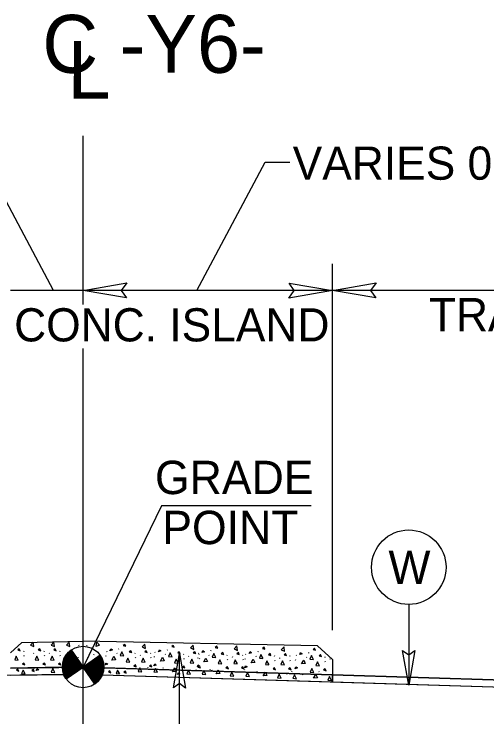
# Model space of a CAD drawing. Extents: x 2176156 to 2177167, y 76401 to 76644.
# Drawn here: x 2176833.29 to 2176849.74, y 76416.24 to 76440.68 of the extents above; entities that cross this region are included whole.
import ezdxf

# ---------------------------------------------------------------- set-up
doc = ezdxf.new("R2010")
doc.units = 0
for name, color, linetype in [('Exist Roads Change in Surface', 7, 'Continuous'), ('Exist Roads Curbs', 7, 'Continuous'), ('Exist Roads Soil', 7, 'Continuous'), ('Exist Structure Minor Culvert Topo', 7, 'Continuous'), ('Exist Vegetation Woods Line', 7, 'Continuous'), ('Old_Level_1', 7, 'Continuous'), ('Old_Level_3', 7, 'Continuous'), ('Prop North Arrow NAD83 for Plan Sheets CELL', 7, 'Continuous')]:
    doc.layers.add(name, color=color, linetype=linetype)

msp = doc.modelspace()

# ---------------------------------------------------------------- linework, layer by layer
at = {"layer": 'Exist Roads Change in Surface'}
for p, q in [((2176835.558, 76418.709), (2176835.547, 76418.733)), ((2176835.825, 76418.709), (2176835.835, 76418.733)), ((2176836.937, 76418.605), (2176836.926, 76418.589)), ((2176833.627, 76418.52), (2176833.617, 76418.504)), ((2176833.647, 76418.345), (2176833.637, 76418.369)), ((2176833.981, 76418.453), (2176833.971, 76418.437)), ((2176834.34, 76418.52), (2176834.329, 76418.504)), ((2176834.36, 76418.345), (2176834.35, 76418.369)), ((2176834.521, 76418.453), (2176834.51, 76418.437)), ((2176834.88, 76418.52), (2176834.869, 76418.504)), ((2176834.9, 76418.345), (2176834.889, 76418.369)), ((2176835.279, 76418.564), (2176835.691, 76417.972)), ((2176835.315, 76418.4), (2176835.305, 76418.424)), ((2176835.691, 76417.972), (2176836.283, 76418.384)), ((2176836.067, 76418.4), (2176836.078, 76418.424)), ((2176836.483, 76418.345), (2176836.493, 76418.369)), ((2176836.503, 76418.52), (2176836.514, 76418.504)), ((2176836.862, 76418.453), (2176836.872, 76418.437)), ((2176837.505, 76418.453), (2176837.494, 76418.437)), ((2176837.686, 76418.385), (2176837.675, 76418.369)), ((2176838.044, 76418.453), (2176838.034, 76418.437)), ((2176838.191, 76418.487), (2176838.202, 76418.471)), ((2176838.55, 76418.419), (2176838.561, 76418.403)), ((2176838.625, 76418.572), (2176838.615, 76418.556)), ((2176839.193, 76418.419), (2176839.183, 76418.403)), ((2176839.374, 76418.351), (2176839.363, 76418.335)), ((2176839.707, 76418.456), (2176839.717, 76418.44)), ((2176839.733, 76418.419), (2176839.722, 76418.403)), ((2176840.065, 76418.388), (2176840.076, 76418.372)), ((2176840.141, 76418.541), (2176840.13, 76418.525)), ((2176840.709, 76418.389), (2176840.698, 76418.373)), ((2176841.248, 76418.389), (2176841.237, 76418.373)), ((2176841.348, 76418.423), (2176841.359, 76418.407)), ((2176841.707, 76418.356), (2176841.718, 76418.34)), ((2176841.782, 76418.508), (2176841.772, 76418.492)), ((2176842.35, 76418.356), (2176842.34, 76418.34)), ((2176842.89, 76418.356), (2176842.879, 76418.34)), ((2176843.106, 76418.388), (2176843.117, 76418.372)), ((2176843.54, 76418.473), (2176843.529, 76418.457)), ((2176835.198, 76418.113), (2176835.187, 76418.097)), ((2176835.531, 76418.283), (2176835.52, 76418.307)), ((2176835.851, 76418.283), (2176835.862, 76418.307)), ((2176836.184, 76418.113), (2176836.195, 76418.097)), ((2176837.525, 76418.277), (2176837.515, 76418.301)), ((2176838.065, 76418.277), (2176838.054, 76418.301)), ((2176838.171, 76418.311), (2176838.182, 76418.335)), ((2176839.213, 76418.243), (2176839.203, 76418.267)), ((2176839.686, 76418.281), (2176839.697, 76418.305)), ((2176839.753, 76418.243), (2176839.742, 76418.267)), ((2176840.729, 76418.213), (2176840.718, 76418.237)), ((2176840.889, 76418.321), (2176840.879, 76418.305)), ((2176841.268, 76418.213), (2176841.258, 76418.237)), ((2176841.328, 76418.248), (2176841.339, 76418.272)), ((2176842.371, 76418.18), (2176842.36, 76418.204)), ((2176842.531, 76418.288), (2176842.52, 76418.272)), ((2176842.91, 76418.18), (2176842.899, 76418.204)), ((2176843.086, 76418.213), (2176843.096, 76418.237)), ((2176843.465, 76418.32), (2176843.476, 76418.304)), ((2176844.108, 76418.321), (2176844.097, 76418.305)), ((2176844.128, 76418.145), (2176844.118, 76418.169)), ((2176844.289, 76418.253), (2176844.278, 76418.237)), ((2176835.099, 76417.561), (2176835.691, 76417.972)), ((2176835.691, 76417.972), (2176835.099, 76417.561)), ((2176836.103, 76417.38), (2176835.691, 76417.972)), ((2176837.952, 76417.929), (2176837.942, 76417.953)), ((2176838.491, 76417.915), (2176838.481, 76417.939)), ((2176839.639, 76417.852), (2176839.629, 76417.876)), ((2176840.112, 76417.877), (2176840.124, 76417.901)), ((2176840.178, 76417.838), (2176840.168, 76417.862)), ((2176841.316, 76417.886), (2176841.305, 76417.871)), ((2176841.153, 76417.783), (2176841.143, 76417.807)), ((2176841.692, 76417.769), (2176841.682, 76417.793)), ((2176841.753, 76417.802), (2176841.764, 76417.826)), ((2176842.793, 76417.708), (2176842.783, 76417.732)), ((2176842.956, 76417.812), (2176842.945, 76417.796)), ((2176843.332, 76417.694), (2176843.322, 76417.718)), ((2176843.509, 76417.722), (2176843.52, 76417.746)), ((2176843.891, 76417.82), (2176843.901, 76417.804))]:
    msp.add_line(p, q, dxfattribs=at)
for points in [[(2176833.505, 76418.539), (2176833.473, 76418.605), (2176833.42, 76418.566), (2176833.505, 76418.539)], [(2176833.981, 76418.682), (2176833.96, 76418.834), (2176833.865, 76418.736), (2176833.979, 76418.683)], [(2176834.218, 76418.539), (2176834.186, 76418.605), (2176834.133, 76418.566), (2176834.218, 76418.539)], [(2176834.694, 76418.682), (2176834.673, 76418.834), (2176834.578, 76418.736), (2176834.692, 76418.683)], [(2176834.757, 76418.539), (2176834.725, 76418.605), (2176834.672, 76418.566), (2176834.757, 76418.539)], [(2176835.234, 76418.682), (2176835.212, 76418.834), (2176835.117, 76418.736), (2176835.231, 76418.683)], [(2176836.149, 76418.682), (2176836.17, 76418.834), (2176836.265, 76418.736), (2176836.151, 76418.683)], [(2176836.625, 76418.539), (2176836.657, 76418.605), (2176836.71, 76418.566), (2176836.625, 76418.539)], [(2176837.174, 76418.692), (2176837.142, 76418.758), (2176837.088, 76418.718), (2176837.174, 76418.692)], [(2176837.859, 76418.614), (2176837.838, 76418.767), (2176837.743, 76418.668), (2176837.857, 76418.615)], [(2176838.862, 76418.658), (2176838.83, 76418.725), (2176838.777, 76418.685), (2176838.862, 76418.658)], [(2176839.547, 76418.581), (2176839.526, 76418.733), (2176839.431, 76418.634), (2176839.545, 76418.581)], [(2176840.377, 76418.628), (2176840.345, 76418.694), (2176840.292, 76418.654), (2176840.377, 76418.628)], [(2176841.063, 76418.55), (2176841.042, 76418.703), (2176840.946, 76418.604), (2176841.06, 76418.551)], [(2176842.019, 76418.595), (2176841.987, 76418.661), (2176841.934, 76418.621), (2176842.019, 76418.595)], [(2176842.704, 76418.517), (2176842.683, 76418.67), (2176842.588, 76418.571), (2176842.702, 76418.518)], [(2176843.777, 76418.56), (2176843.745, 76418.626), (2176843.692, 76418.586), (2176843.777, 76418.56)], [(2176833.438, 76418.212), (2176833.367, 76418.347), (2176833.311, 76418.222), (2176833.436, 76418.212)], [(2176834.151, 76418.212), (2176834.079, 76418.347), (2176834.023, 76418.222), (2176834.149, 76418.212)], [(2176834.691, 76418.212), (2176834.619, 76418.347), (2176834.563, 76418.222), (2176834.688, 76418.212)], [(2176835.43, 76418.348), (2176834.972, 76418.03)], [(2176835.421, 76418.36), (2176834.974, 76418.049)], [(2176835.413, 76418.372), (2176834.977, 76418.068)], [(2176835.405, 76418.383), (2176834.979, 76418.087)], [(2176835.397, 76418.395), (2176834.982, 76418.107)], [(2176835.388, 76418.407), (2176834.987, 76418.128)], [(2176835.38, 76418.419), (2176834.992, 76418.149)], [(2176835.372, 76418.431), (2176834.998, 76418.171)], [(2176835.364, 76418.443), (2176835.005, 76418.193)], [(2176835.355, 76418.454), (2176835.012, 76418.216)], [(2176835.347, 76418.466), (2176835.021, 76418.239)], [(2176835.339, 76418.478), (2176835.031, 76418.264)], [(2176835.331, 76418.49), (2176835.044, 76418.291)], [(2176835.322, 76418.502), (2176835.058, 76418.318)], [(2176835.314, 76418.514), (2176835.075, 76418.347)], [(2176835.306, 76418.525), (2176835.094, 76418.378)], [(2176835.298, 76418.537), (2176835.122, 76418.415)], [(2176835.29, 76418.549), (2176835.155, 76418.456)], [(2176835.281, 76418.561), (2176835.217, 76418.516)], [(2176836.287, 76418.378), (2176836.287, 76418.378), (2176835.695, 76417.967)], [(2176836.295, 76418.367), (2176835.703, 76417.955)], [(2176836.302, 76418.354), (2176835.711, 76417.943)], [(2176836.692, 76418.212), (2176836.764, 76418.347), (2176836.82, 76418.222), (2176836.694, 76418.212)], [(2176837.107, 76418.364), (2176837.035, 76418.5), (2176836.979, 76418.375), (2176837.104, 76418.364)], [(2176837.383, 76418.471), (2176837.351, 76418.538), (2176837.298, 76418.498), (2176837.383, 76418.471)], [(2176837.922, 76418.471), (2176837.89, 76418.538), (2176837.837, 76418.498), (2176837.922, 76418.471)], [(2176838.313, 76418.505), (2176838.345, 76418.572), (2176838.399, 76418.532), (2176838.313, 76418.505)], [(2176838.795, 76418.331), (2176838.723, 76418.467), (2176838.667, 76418.341), (2176838.793, 76418.331)], [(2176839.071, 76418.438), (2176839.039, 76418.504), (2176838.986, 76418.464), (2176839.071, 76418.438)], [(2176839.611, 76418.438), (2176839.579, 76418.504), (2176839.525, 76418.464), (2176839.611, 76418.438)], [(2176839.829, 76418.475), (2176839.861, 76418.541), (2176839.914, 76418.501), (2176839.829, 76418.475)], [(2176840.311, 76418.3), (2176840.239, 76418.436), (2176840.183, 76418.311), (2176840.308, 76418.3)], [(2176840.587, 76418.407), (2176840.555, 76418.474), (2176840.501, 76418.434), (2176840.587, 76418.407)], [(2176841.126, 76418.407), (2176841.094, 76418.474), (2176841.041, 76418.434), (2176841.126, 76418.407)], [(2176841.47, 76418.442), (2176841.502, 76418.509), (2176841.556, 76418.469), (2176841.47, 76418.442)], [(2176841.952, 76418.268), (2176841.88, 76418.403), (2176841.824, 76418.278), (2176841.95, 76418.268)], [(2176842.228, 76418.374), (2176842.196, 76418.441), (2176842.143, 76418.401), (2176842.228, 76418.374)], [(2176842.768, 76418.374), (2176842.736, 76418.441), (2176842.682, 76418.401), (2176842.768, 76418.374)], [(2176843.228, 76418.407), (2176843.26, 76418.473), (2176843.313, 76418.433), (2176843.228, 76418.407)], [(2176843.71, 76418.232), (2176843.638, 76418.368), (2176843.582, 76418.243), (2176843.708, 76418.232)], [(2176843.986, 76418.339), (2176843.954, 76418.406), (2176843.901, 76418.366), (2176843.986, 76418.339)], [(2176833.666, 76418.044), (2176833.634, 76418.11), (2176833.581, 76418.07), (2176833.666, 76418.044)], [(2176834.379, 76418.044), (2176834.347, 76418.11), (2176834.294, 76418.07), (2176834.379, 76418.044)], [(2176834.918, 76418.044), (2176834.886, 76418.11), (2176834.833, 76418.07), (2176834.918, 76418.044)], [(2176835.446, 76418.324), (2176834.97, 76417.993)], [(2176835.454, 76418.312), (2176834.97, 76417.976)], [(2176835.438, 76418.336), (2176834.971, 76418.011)], [(2176835.462, 76418.301), (2176834.971, 76417.958)], [(2176835.471, 76418.289), (2176834.971, 76417.941)], [(2176835.479, 76418.277), (2176834.971, 76417.924)], [(2176835.487, 76418.265), (2176834.973, 76417.907)], [(2176835.495, 76418.253), (2176834.975, 76417.891)], [(2176835.504, 76418.241), (2176834.976, 76417.875)], [(2176835.512, 76418.23), (2176834.979, 76417.859)], [(2176835.52, 76418.218), (2176834.982, 76417.844)], [(2176835.528, 76418.206), (2176834.985, 76417.828)], [(2176835.537, 76418.194), (2176834.988, 76417.813)], [(2176835.545, 76418.182), (2176834.991, 76417.797)], [(2176835.553, 76418.17), (2176834.996, 76417.783)], [(2176835.561, 76418.159), (2176835, 76417.768)], [(2176835.57, 76418.147), (2176835.004, 76417.753)], [(2176835.578, 76418.135), (2176835.01, 76417.74)], [(2176835.586, 76418.123), (2176835.014, 76417.725)], [(2176835.594, 76418.111), (2176835.02, 76417.711)], [(2176836.31, 76418.342), (2176835.72, 76417.931)], [(2176836.317, 76418.329), (2176835.728, 76417.919)], [(2176836.324, 76418.317), (2176835.736, 76417.908)], [(2176836.331, 76418.304), (2176835.744, 76417.896)], [(2176836.338, 76418.291), (2176835.753, 76417.884)], [(2176836.345, 76418.278), (2176835.761, 76417.872)], [(2176836.35, 76418.265), (2176835.769, 76417.86)], [(2176836.356, 76418.251), (2176835.777, 76417.848)], [(2176836.361, 76418.237), (2176835.785, 76417.836)], [(2176836.367, 76418.224), (2176835.794, 76417.825)], [(2176836.371, 76418.209), (2176835.802, 76417.813)], [(2176836.377, 76418.195), (2176835.81, 76417.801)], [(2176836.381, 76418.181), (2176835.818, 76417.789)], [(2176836.385, 76418.166), (2176835.827, 76417.777)], [(2176836.39, 76418.152), (2176835.835, 76417.765)], [(2176836.393, 76418.136), (2176835.843, 76417.754)], [(2176836.396, 76418.121), (2176835.851, 76417.742)], [(2176836.399, 76418.105), (2176835.86, 76417.73)], [(2176836.464, 76418.044), (2176836.496, 76418.11), (2176836.549, 76418.07), (2176836.464, 76418.044)], [(2176837.316, 76418.144), (2176837.244, 76418.28), (2176837.188, 76418.155), (2176837.314, 76418.144)], [(2176837.856, 76418.144), (2176837.784, 76418.28), (2176837.728, 76418.155), (2176837.853, 76418.144)], [(2176838.38, 76418.178), (2176838.452, 76418.314), (2176838.508, 76418.188), (2176838.383, 76418.178)], [(2176839.005, 76418.11), (2176838.933, 76418.246), (2176838.877, 76418.121), (2176839.002, 76418.11)], [(2176839.544, 76418.11), (2176839.472, 76418.246), (2176839.416, 76418.121), (2176839.541, 76418.11)], [(2176839.895, 76418.147), (2176839.967, 76418.283), (2176840.023, 76418.158), (2176839.898, 76418.147)], [(2176840.52, 76418.08), (2176840.448, 76418.216), (2176840.392, 76418.091), (2176840.517, 76418.08)], [(2176841.059, 76418.08), (2176840.987, 76418.216), (2176840.931, 76418.091), (2176841.057, 76418.08)], [(2176841.537, 76418.115), (2176841.609, 76418.25), (2176841.665, 76418.125), (2176841.54, 76418.115)], [(2176842.162, 76418.047), (2176842.09, 76418.183), (2176842.034, 76418.058), (2176842.159, 76418.047)], [(2176842.701, 76418.047), (2176842.629, 76418.183), (2176842.573, 76418.058), (2176842.698, 76418.047)], [(2176843.295, 76418.079), (2176843.367, 76418.215), (2176843.423, 76418.09), (2176843.297, 76418.079)], [(2176843.919, 76418.012), (2176843.847, 76418.148), (2176843.791, 76418.023), (2176843.917, 76418.012)], [(2176833.455, 76417.833), (2176833.425, 76417.901), (2176833.371, 76417.862), (2176833.455, 76417.833)], [(2176833.674, 76417.73), (2176833.602, 76417.866), (2176833.546, 76417.741), (2176833.671, 76417.73)], [(2176833.994, 76417.819), (2176833.964, 76417.887), (2176833.91, 76417.848), (2176833.994, 76417.819)], [(2176834.064, 76417.851), (2176834.098, 76417.917), (2176834.15, 76417.876), (2176834.064, 76417.851)], [(2176834.71, 76417.786), (2176834.638, 76417.922), (2176834.582, 76417.797), (2176834.707, 76417.786)], [(2176835.602, 76418.099), (2176835.025, 76417.698)], [(2176835.611, 76418.088), (2176835.031, 76417.684)], [(2176835.619, 76418.076), (2176835.036, 76417.67)], [(2176835.627, 76418.064), (2176835.043, 76417.658)], [(2176835.635, 76418.052), (2176835.049, 76417.644)], [(2176835.644, 76418.04), (2176835.056, 76417.631)], [(2176835.652, 76418.028), (2176835.063, 76417.619)], [(2176835.66, 76418.017), (2176835.07, 76417.606)], [(2176835.668, 76418.005), (2176835.078, 76417.594)], [(2176835.677, 76417.993), (2176835.085, 76417.581)], [(2176835.685, 76417.981), (2176835.093, 76417.569), (2176835.093, 76417.569)], [(2176836.402, 76418.09), (2176835.868, 76417.718)], [(2176836.405, 76418.074), (2176835.876, 76417.706)], [(2176836.406, 76418.058), (2176835.884, 76417.695)], [(2176836.408, 76418.041), (2176835.893, 76417.683)], [(2176836.41, 76418.025), (2176835.901, 76417.671)], [(2176836.411, 76418.009), (2176835.909, 76417.659)], [(2176836.412, 76417.991), (2176835.917, 76417.647)], [(2176836.412, 76417.974), (2176835.925, 76417.635)], [(2176836.411, 76417.956), (2176835.934, 76417.623)], [(2176836.411, 76417.938), (2176835.942, 76417.612)], [(2176836.41, 76417.92), (2176835.95, 76417.6)], [(2176836.408, 76417.901), (2176835.958, 76417.588)], [(2176836.406, 76417.882), (2176835.967, 76417.576)], [(2176836.404, 76417.863), (2176835.975, 76417.564)], [(2176836.966, 76417.73), (2176836.894, 76417.866), (2176836.838, 76417.741), (2176836.964, 76417.73)], [(2176837.544, 76417.976), (2176837.512, 76418.043), (2176837.459, 76418.003), (2176837.544, 76417.976)], [(2176837.74, 76417.801), (2176837.671, 76417.938), (2176837.612, 76417.815), (2176837.737, 76417.801)], [(2176838.083, 76417.976), (2176838.051, 76418.043), (2176837.998, 76418.003), (2176838.083, 76417.976)], [(2176838.279, 76417.787), (2176838.21, 76417.925), (2176838.151, 76417.801), (2176838.276, 76417.787)], [(2176838.152, 76418.01), (2176838.184, 76418.077), (2176838.238, 76418.037), (2176838.152, 76418.01)], [(2176838.804, 76417.807), (2176838.879, 76417.941), (2176838.932, 76417.815), (2176838.806, 76417.807)], [(2176839.232, 76417.942), (2176839.2, 76418.009), (2176839.147, 76417.969), (2176839.232, 76417.942)], [(2176839.426, 76417.724), (2176839.358, 76417.862), (2176839.299, 76417.738), (2176839.424, 76417.724)], [(2176839.668, 76417.98), (2176839.7, 76418.046), (2176839.753, 76418.006), (2176839.668, 76417.98)], [(2176839.772, 76417.942), (2176839.74, 76418.009), (2176839.686, 76417.969), (2176839.772, 76417.942)], [(2176840.318, 76417.738), (2176840.393, 76417.872), (2176840.446, 76417.746), (2176840.321, 76417.738)], [(2176840.748, 76417.912), (2176840.716, 76417.979), (2176840.662, 76417.939), (2176840.748, 76417.912)], [(2176841.287, 76417.912), (2176841.255, 76417.979), (2176841.202, 76417.939), (2176841.287, 76417.912)], [(2176841.309, 76417.947), (2176841.341, 76418.013), (2176841.395, 76417.973), (2176841.309, 76417.947)], [(2176842.389, 76417.879), (2176842.357, 76417.946), (2176842.304, 76417.906), (2176842.389, 76417.879)], [(2176842.929, 76417.879), (2176842.897, 76417.946), (2176842.843, 76417.906), (2176842.929, 76417.879)], [(2176843.067, 76417.912), (2176843.099, 76417.978), (2176843.152, 76417.938), (2176843.067, 76417.912)], [(2176843.721, 76417.781), (2176843.649, 76417.917), (2176843.593, 76417.792), (2176843.718, 76417.781)], [(2176844.147, 76417.844), (2176844.115, 76417.911), (2176844.062, 76417.871), (2176844.147, 76417.844)], [(2176836.4, 76417.843), (2176835.983, 76417.553)], [(2176836.396, 76417.822), (2176835.991, 76417.541)], [(2176836.391, 76417.802), (2176836, 76417.529)], [(2176836.385, 76417.78), (2176836.008, 76417.517)], [(2176836.379, 76417.758), (2176836.016, 76417.505)], [(2176836.371, 76417.735), (2176836.024, 76417.493)], [(2176836.363, 76417.711), (2176836.033, 76417.481)], [(2176836.352, 76417.686), (2176836.041, 76417.47)], [(2176836.341, 76417.661), (2176836.049, 76417.458)], [(2176836.328, 76417.635), (2176836.057, 76417.446)], [(2176836.656, 76417.774), (2176836.626, 76417.842), (2176836.572, 76417.803), (2176836.656, 76417.774)], [(2176837.195, 76417.76), (2176837.165, 76417.828), (2176837.111, 76417.789), (2176837.195, 76417.76)], [(2176838.975, 76417.714), (2176839.009, 76417.78), (2176839.061, 76417.739), (2176838.975, 76417.714)], [(2176839.966, 76417.71), (2176839.897, 76417.848), (2176839.838, 76417.724), (2176839.963, 76417.71)], [(2176840.941, 76417.655), (2176840.872, 76417.793), (2176840.813, 76417.669), (2176840.938, 76417.655)], [(2176841.48, 76417.641), (2176841.411, 76417.779), (2176841.352, 76417.655), (2176841.477, 76417.641)], [(2176841.958, 76417.664), (2176842.034, 76417.798), (2176842.086, 76417.671), (2176841.961, 76417.664)], [(2176842.581, 76417.58), (2176842.512, 76417.718), (2176842.453, 76417.594), (2176842.578, 76417.58)], [(2176843.12, 76417.566), (2176843.052, 76417.704), (2176842.992, 76417.58), (2176843.117, 76417.566)], [(2176843.714, 76417.584), (2176843.79, 76417.717), (2176843.843, 76417.591), (2176843.717, 76417.583)], [(2176844.337, 76417.5), (2176844.269, 76417.638), (2176844.21, 76417.514), (2176844.334, 76417.5)], [(2176836.311, 76417.605), (2176836.065, 76417.434)], [(2176836.292, 76417.574), (2176836.074, 76417.422)], [(2176836.267, 76417.539), (2176836.082, 76417.41)], [(2176836.235, 76417.499), (2176836.09, 76417.399)], [(2176836.183, 76417.445), (2176836.098, 76417.387)]]:
    msp.add_lwpolyline(points, dxfattribs=at)
msp.add_circle((2176835.691, 76417.973), 0.721, dxfattribs=at)
for start, end in [(124.8249, 214.8249), (304.8249, 34.8249)]:
    msp.add_arc((2176835.691, 76417.973), 0.721, start, end, dxfattribs=at)
at = {"layer": 'Exist Roads Curbs'}
for p, q in [((2176833.161, 76417.934), (2176835.691, 76417.972)), ((2176834.97, 76417.961), (2176833.161, 76417.934)), ((2176834.971, 76417.924), (2176834.972, 76417.924)), ((2176834.976, 76417.875), (2176834.977, 76417.875)), ((2176835.691, 76417.972), (2176844.366, 76417.701)), ((2176836.404, 76417.863), (2176836.403, 76417.862)), ((2176836.41, 76417.92), (2176836.41, 76417.92)), ((2176844.366, 76417.701), (2176836.411, 76417.949)), ((2176836.411, 76417.938), (2176836.411, 76417.938)), ((2176835.019, 76417.712), (2176820.906, 76417.502)), ((2176833.161, 76417.684), (2176835.019, 76417.712)), ((2176834.991, 76417.797), (2176834.992, 76417.797)), ((2176834.996, 76417.783), (2176834.996, 76417.783)), ((2176835.004, 76417.753), (2176835.004, 76417.753)), ((2176836.359, 76417.701), (2176856.626, 76417.069)), ((2176836.359, 76417.701), (2176844.366, 76417.451)), ((2176836.371, 76417.735), (2176836.371, 76417.735)), ((2176836.379, 76417.758), (2176836.379, 76417.758)), ((2176836.391, 76417.802), (2176836.391, 76417.801)), ((2176836.396, 76417.822), (2176836.396, 76417.822)), ((2176836.4, 76417.843), (2176836.4, 76417.843)), ((2176844.366, 76417.701), (2176860.366, 76417.202)), ((2176860.366, 76417.202), (2176844.366, 76417.701)), ((2176844.366, 76417.701), (2176844.366, 76417.451)), ((2176844.366, 76417.451), (2176844.366, 76417.701)), ((2176844.366, 76417.451), (2176852.548, 76417.196))]:
    msp.add_line(p, q, dxfattribs=at)
for points in [[(2176834.972, 76417.924), (2176834.971, 76417.924)], [(2176834.977, 76417.875), (2176834.976, 76417.875)], [(2176836.403, 76417.863), (2176836.404, 76417.863)], [(2176836.41, 76417.92), (2176836.41, 76417.92)], [(2176836.411, 76417.938), (2176836.411, 76417.938)], [(2176834.992, 76417.797), (2176834.991, 76417.797)], [(2176834.996, 76417.783), (2176834.996, 76417.783)], [(2176835.004, 76417.753), (2176835.004, 76417.753)], [(2176836.371, 76417.735), (2176836.371, 76417.735)], [(2176836.379, 76417.758), (2176836.379, 76417.758)], [(2176836.391, 76417.802), (2176836.391, 76417.802)], [(2176836.396, 76417.823), (2176836.396, 76417.822)], [(2176836.4, 76417.843), (2176836.4, 76417.843)], [(2176844.366, 76417.451), (2176844.366, 76417.451)]]:
    msp.add_lwpolyline(points, dxfattribs=at)
for start, end in [(180.9136, 181.1347), (181.1347, 182.5146), (182.5146, 183.8761), (183.8895, 185.2021), (185.2021, 186.5121), (186.5121, 187.8094), (187.8245, 190.3336), (349.5984, 351.2038), (351.2196, 354.2837), (354.2837, 355.7778), (355.8127, 357.2394), (357.2652, 358.1523), (190.3336, 191.5882), (191.5882, 192.8361), (192.8361, 194.0754), (194.0907, 195.2968), (195.2976, 196.5055), (196.5055, 197.7127), (197.7154, 200.0946), (200.0946, 201.2126), (337.8613, 338.7193), (338.7193, 340.731), (340.7368, 342.6429), (342.646, 344.4557), (344.4557, 346.2404), (346.2648, 347.9455), (347.9775, 349.598)]:
    msp.add_arc((2176835.691, 76417.973), 0.721, start, end, dxfattribs=at)
at = {"layer": 'Exist Roads Soil'}
for p, q in [((2176833.556, 76418.829), (2176835.691, 76418.872)), ((2176843.85, 76418.709), (2176835.691, 76418.872)), ((2176833.161, 76418.465), (2176833.556, 76418.829)), ((2176844.366, 76418.232), (2176843.85, 76418.709)), ((2176844.366, 76418.232), (2176844.366, 76417.451))]:
    msp.add_line(p, q, dxfattribs=at)
at = {"layer": 'Old_Level_1'}
for points in [[(2176837.201, 76430.805), (2176835.691, 76431.065), (2176837.209, 76431.333), (2176837.016, 76431.065)], [(2176842.857, 76431.325), (2176844.366, 76431.065), (2176842.848, 76430.796), (2176843.041, 76431.065)], [(2176845.876, 76430.805), (2176844.366, 76431.065), (2176845.884, 76431.333), (2176845.691, 76431.065)]]:
    msp.add_lwpolyline(points, close=True, dxfattribs=at)
at = {"layer": 'Old_Level_3'}
for p, q in [((2176835.691, 76431.863), (2176835.691, 76436.448)), ((2176834.662, 76431.065), (2176832.287, 76435.525)), ((2176839.651, 76431.065), (2176842.026, 76435.525)), ((2176842.026, 76435.525), (2176842.89, 76435.525)), ((2176835.691, 76430.582), (2176835.691, 76431.863)), ((2176844.366, 76419.328), (2176844.366, 76431.992)), ((2176844.366, 76419.252), (2176844.366, 76431.949)), ((2176844.366, 76431.065), (2176833.161, 76431.065)), ((2176860.366, 76431.065), (2176844.366, 76431.065)), ((2176835.691, 76410.033), (2176835.691, 76429.049))]:
    msp.add_line(p, q, dxfattribs=at)
at = {"layer": 'Prop North Arrow NAD83 for Plan Sheets CELL'}
for p, q in [((2176838.415, 76423.58), (2176835.691, 76417.972)), ((2176843.633, 76423.58), (2176838.415, 76423.58)), ((2176847.023, 76420.146), (2176847.023, 76417.342)), ((2176839.043, 76414.681), (2176839.043, 76418.446))]:
    msp.add_line(p, q, dxfattribs=at)
for points in [[(2176838.836, 76417.246), (2176839.043, 76418.446), (2176839.256, 76417.24), (2176839.043, 76417.393)], [(2176847.23, 76418.542), (2176847.023, 76417.342), (2176846.81, 76418.549), (2176847.023, 76418.396)]]:
    msp.add_lwpolyline(points, close=True, dxfattribs=at)
msp.add_circle((2176847.023, 76421.442), 1.296, dxfattribs=at)

# ---------------------------------------------------------------- texts
at = {"layer": 'Exist Structure Minor Culvert Topo'}
for s, p in [("VARIES 0'-23'", (2176842.984, 76434.918)), ('TRAVEL LANE', (2176847.725, 76429.651)), ('CONC. ISLAND', (2176833.294, 76429.295))]:
    msp.add_text(s, height=1.15334, dxfattribs=at).set_placement(p)
at = {"layer": 'Exist Vegetation Woods Line'}
msp.add_text('C -Y6-', height=2.0131, dxfattribs=at).set_placement((2176834.271, 76438.636))
msp.add_text('L', height=2.013, rotation=359.9469, dxfattribs=at).set_placement((2176835.148, 76437.735))
at = {"layer": 'Prop North Arrow NAD83 for Plan Sheets CELL'}
for s, rotation, p in [('GRADE', 0.0002, (2176838.193, 76423.985)), ('POINT', 0.0002, (2176838.446, 76422.245)), ('W', 0.0003, (2176846.315, 76420.862))]:
    msp.add_text(s, height=1.16, rotation=rotation, dxfattribs=at).set_placement(p)

doc.saveas('drawing.dxf')
